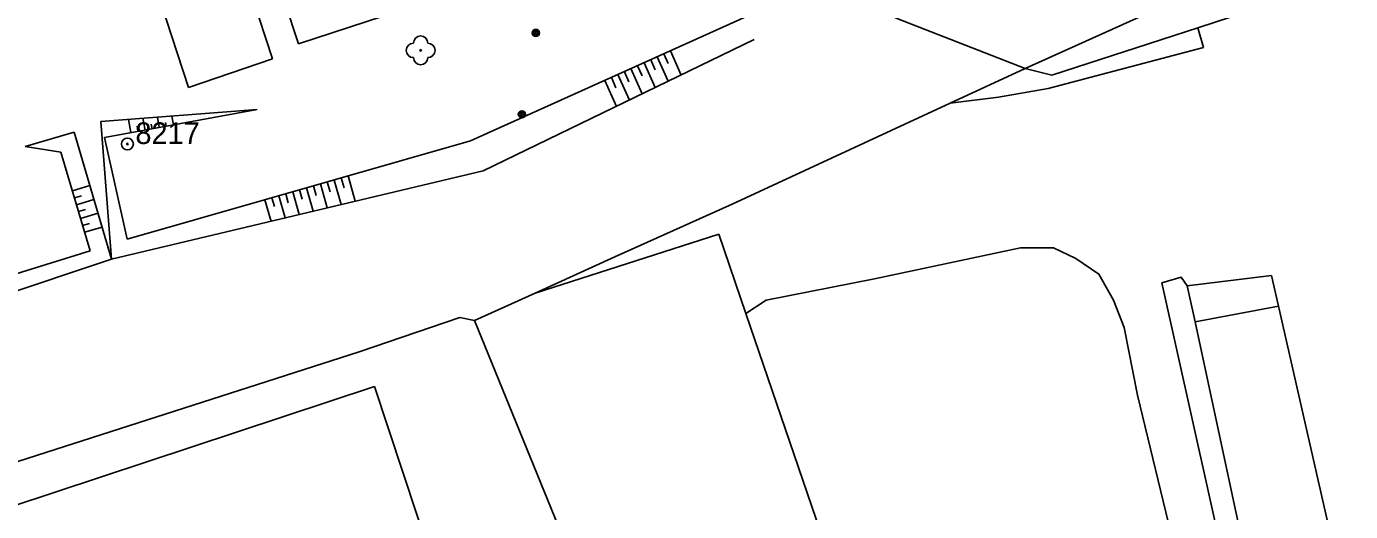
# Model space of a CAD drawing. Extents: x -493753 to -49290, y -1127285 to -112654.
# Drawn here: x -493245.2 to -493153.3, y -1126783.5 to -1126749.8 of the extents above; entities that cross this region are included whole.
import ezdxf

# ---------------------------------------------------------------- set-up
doc = ezdxf.new("R2010")
doc.units = 0
for name, color, linetype in [('Vrstva 11', 7, 'Continuous'), ('Vrstva 14', 7, 'Continuous'), ('Vrstva 15', 7, 'Continuous'), ('Vrstva 22', 7, 'Continuous'), ('Vrstva 25', 7, 'Continuous'), ('Vrstva 5', 7, 'Continuous'), ('Vrstva 63', 7, 'Continuous')]:
    doc.layers.add(name, color=color, linetype=linetype)

msp = doc.modelspace()

# ---------------------------------------------------------------- linework, layer by layer
at = {"layer": 'Vrstva 11'}
for points in [[(-493163.87, -1126749.94), (-493145.29, -1126743.84), (-493136.28, -1126740.84), (-493125, -1126737.46)], [(-493154.83, -1126743.28), (-493175.84, -1126752.77)], [(-493190.87, -1126744.55), (-493189.81, -1126746), (-493188.71, -1126747.45), (-493184.68, -1126749.31), (-493175.84, -1126752.77)], [(-493173.99, -1126753.21), (-493163.87, -1126749.94)], [(-493163.87, -1126749.94), (-493163.47, -1126751.29)], [(-493163.47, -1126751.29), (-493174.25, -1126754.15)], [(-493181.06, -1126755.16), (-493175.84, -1126752.77)], [(-493175.84, -1126752.77), (-493173.99, -1126753.21)], [(-493174.25, -1126754.15), (-493177.69, -1126754.74)], [(-493181.06, -1126755.16), (-493196.19, -1126762.17)], [(-493177.69, -1126754.74), (-493181.06, -1126755.16)], [(-493196.19, -1126762.17), (-493204.33, -1126765.84)], [(-493197.12, -1126764.27), (-493209.88, -1126768.35)], [(-493195.24, -1126769.77), (-493197.12, -1126764.27)], [(-493193.84, -1126768.85), (-493186.31, -1126767.37), (-493176.17, -1126765.22), (-493173.89, -1126765.22), (-493172.34, -1126765.96), (-493170.73, -1126767.03), (-493169.72, -1126768.85), (-493168.98, -1126770.73), (-493168.04, -1126775.44), (-493161.79, -1126801.25), (-493158.31, -1126816.15), (-493158.51, -1126818.36), (-493159.11, -1126820.3), (-493160.05, -1126821.85), (-493160.86, -1126822.73), (-493162.27, -1126823.46), (-493168.52, -1126825.08), (-493175.86, -1126826.9)], [(-493204.33, -1126765.84), (-493209.88, -1126768.35)], [(-493158.75, -1126767.12), (-493164.59, -1126767.84)], [(-493158.27, -1126769.26), (-493158.75, -1126767.12)], [(-493154.07, -1126818.67), (-493154.81, -1126818.16), (-493155.01, -1126817.83), (-493155.41, -1126816.82), (-493156.08, -1126813.52), (-493159.98, -1126796.31), (-493166.36, -1126767.64), (-493165.02, -1126767.24), (-493164.59, -1126767.84)], [(-493164.59, -1126767.84), (-493164.05, -1126770.35)], [(-493214.08, -1126770.25), (-493209.88, -1126768.35)], [(-493193.84, -1126768.85), (-493195.24, -1126769.77)], [(-493187.92, -1126791.15), (-493195.24, -1126769.77)], [(-493158.27, -1126769.26), (-493164.05, -1126770.35)], [(-493154.8, -1126784.51), (-493158.27, -1126769.26)], [(-493222.08, -1126772.42), (-493215.11, -1126770.05)], [(-493215.11, -1126770.05), (-493214.08, -1126770.25)], [(-493200.32, -1126804.01), (-493214.08, -1126770.25)], [(-493164.05, -1126770.35), (-493160.9, -1126785.03)], [(-493261.8, -1126785.18), (-493222.08, -1126772.42)], [(-493268.53, -1126790.54), (-493221.02, -1126774.83)], [(-493221.02, -1126774.83), (-493216.11, -1126789.67)]]:
    msp.add_lwpolyline(points, dxfattribs=at)
at = {"layer": 'Vrstva 14'}
for p, q in [((-493195.19, -1126749.16), (-493214.37, -1126757.79)), ((-493213.49, -1126759.87), (-493194.66, -1126750.75)), ((-493229.16, -1126755.61), (-493240.02, -1126756.43)), ((-493229.16, -1126755.61), (-493239.76, -1126757.54)), ((-493239.28, -1126766), (-493240.02, -1126756.43)), ((-493245.27, -1126758.18), (-493241.87, -1126757.19)), ((-493241.87, -1126757.19), (-493239.28, -1126766)), ((-493239.76, -1126757.54), (-493238.19, -1126764.61)), ((-493214.37, -1126757.79), (-493238.19, -1126764.61)), ((-493242.8, -1126758.57), (-493245.27, -1126758.18)), ((-493240.77, -1126765.42), (-493242.8, -1126758.57)), ((-493239.28, -1126766), (-493213.49, -1126759.87)), ((-493240.77, -1126765.42), (-493323.21, -1126790.89)), ((-493239.28, -1126766), (-493322.79, -1126793.72))]:
    msp.add_line(p, q, dxfattribs=at)
at = {"layer": 'Vrstva 15'}
for p, q in [((-493202.3, -1126752.36), (-493201.53, -1126754.08)), ((-493201.85, -1126752.16), (-493201.54, -1126752.84)), ((-493201.39, -1126751.95), (-493200.63, -1126753.64)), ((-493200.94, -1126751.75), (-493200.63, -1126752.42)), ((-493200.48, -1126751.54), (-493199.73, -1126753.21)), ((-493204.13, -1126753.18), (-493203.33, -1126754.95)), ((-493203.67, -1126752.98), (-493203.36, -1126753.68)), ((-493203.22, -1126752.77), (-493202.43, -1126754.52)), ((-493202.76, -1126752.57), (-493202.45, -1126753.26)), ((-493205.04, -1126753.59), (-493204.23, -1126755.39)), ((-493204.58, -1126753.39), (-493204.26, -1126754.1)), ((-493234.99, -1126756.67), (-493235.1, -1126756.06)), ((-493237.94, -1126757.21), (-493238.11, -1126756.29)), ((-493237.45, -1126757.12), (-493237.51, -1126756.77)), ((-493236.95, -1126757.03), (-493237.1, -1126756.21)), ((-493236.46, -1126756.94), (-493236.52, -1126756.63)), ((-493235.97, -1126756.85), (-493236.1, -1126756.13)), ((-493235.48, -1126756.76), (-493235.53, -1126756.5)), ((-493224.3, -1126760.63), (-493224.11, -1126761.31)), ((-493223.82, -1126760.5), (-493223.33, -1126762.21)), ((-493223.34, -1126760.36), (-493223.14, -1126761.05)), ((-493222.86, -1126760.22), (-493222.36, -1126761.98)), ((-493242, -1126761.26), (-493240.78, -1126760.89)), ((-493241.86, -1126761.74), (-493241.37, -1126761.59)), ((-493227.66, -1126761.6), (-493227.22, -1126763.13)), ((-493227.18, -1126761.46), (-493227.01, -1126762.08)), ((-493226.7, -1126761.32), (-493226.25, -1126762.9)), ((-493226.22, -1126761.18), (-493226.04, -1126761.83)), ((-493225.74, -1126761.05), (-493225.28, -1126762.67)), ((-493225.26, -1126760.91), (-493225.07, -1126761.57)), ((-493224.78, -1126760.77), (-493224.3, -1126762.44)), ((-493241.72, -1126762.22), (-493240.5, -1126761.85)), ((-493241.58, -1126762.69), (-493241.09, -1126762.55)), ((-493228.63, -1126761.87), (-493228.2, -1126763.37)), ((-493228.15, -1126761.73), (-493227.97, -1126762.34)), ((-493241.44, -1126763.17), (-493240.22, -1126762.81)), ((-493241.29, -1126763.65), (-493240.81, -1126763.51)), ((-493241.15, -1126764.13), (-493239.94, -1126763.77))]:
    msp.add_line(p, q, dxfattribs=at)
at = {"layer": 'Vrstva 22'}
msp.add_circle((-493217.82, -1126751.5), 0.05, dxfattribs=at)
for centre, start, end in [((-493217.82, -1126751), 0, 180), ((-493218.32, -1126751.5), 90, 270), ((-493217.32, -1126751.5), 270, 90), ((-493217.82, -1126752), 180, 0)]:
    msp.add_arc(centre, 0.5, start, end, dxfattribs=at)
at = {"layer": 'Vrstva 25'}
for centre, radius in [((-493209.82, -1126750.29), 0.25), ((-493209.82, -1126750.29), 0.158), ((-493209.82, -1126750.29), 0.05), ((-493210.79, -1126755.94), 0.25), ((-493210.79, -1126755.94), 0.158), ((-493210.79, -1126755.94), 0.05)]:
    msp.add_circle(centre, radius, dxfattribs=at)
at = {"layer": 'Vrstva 5'}
for p, q in [((-493228.1, -1126752.09), (-493243.91, -1126703.69)), ((-493226.31, -1126751.04), (-493227.24, -1126748.18)), ((-493226.31, -1126751.04), (-493220.42, -1126749.13)), ((-493228.1, -1126752.09), (-493233.93, -1126754.08))]:
    msp.add_line(p, q, dxfattribs=at)
msp.add_lwpolyline([(-493233.93, -1126754.08), (-493249.78, -1126705.63), (-493243.91, -1126703.69)], dxfattribs=at)
at = {"layer": 'Vrstva 63'}
for radius in [0.412, 0.05]:
    msp.add_circle((-493238.18, -1126758), radius, dxfattribs=at)

# ---------------------------------------------------------------- texts
msp.add_text(' 8217', height=1.5, dxfattribs=at).set_placement((-493238.18, -1126758))

doc.saveas('drawing.dxf')
